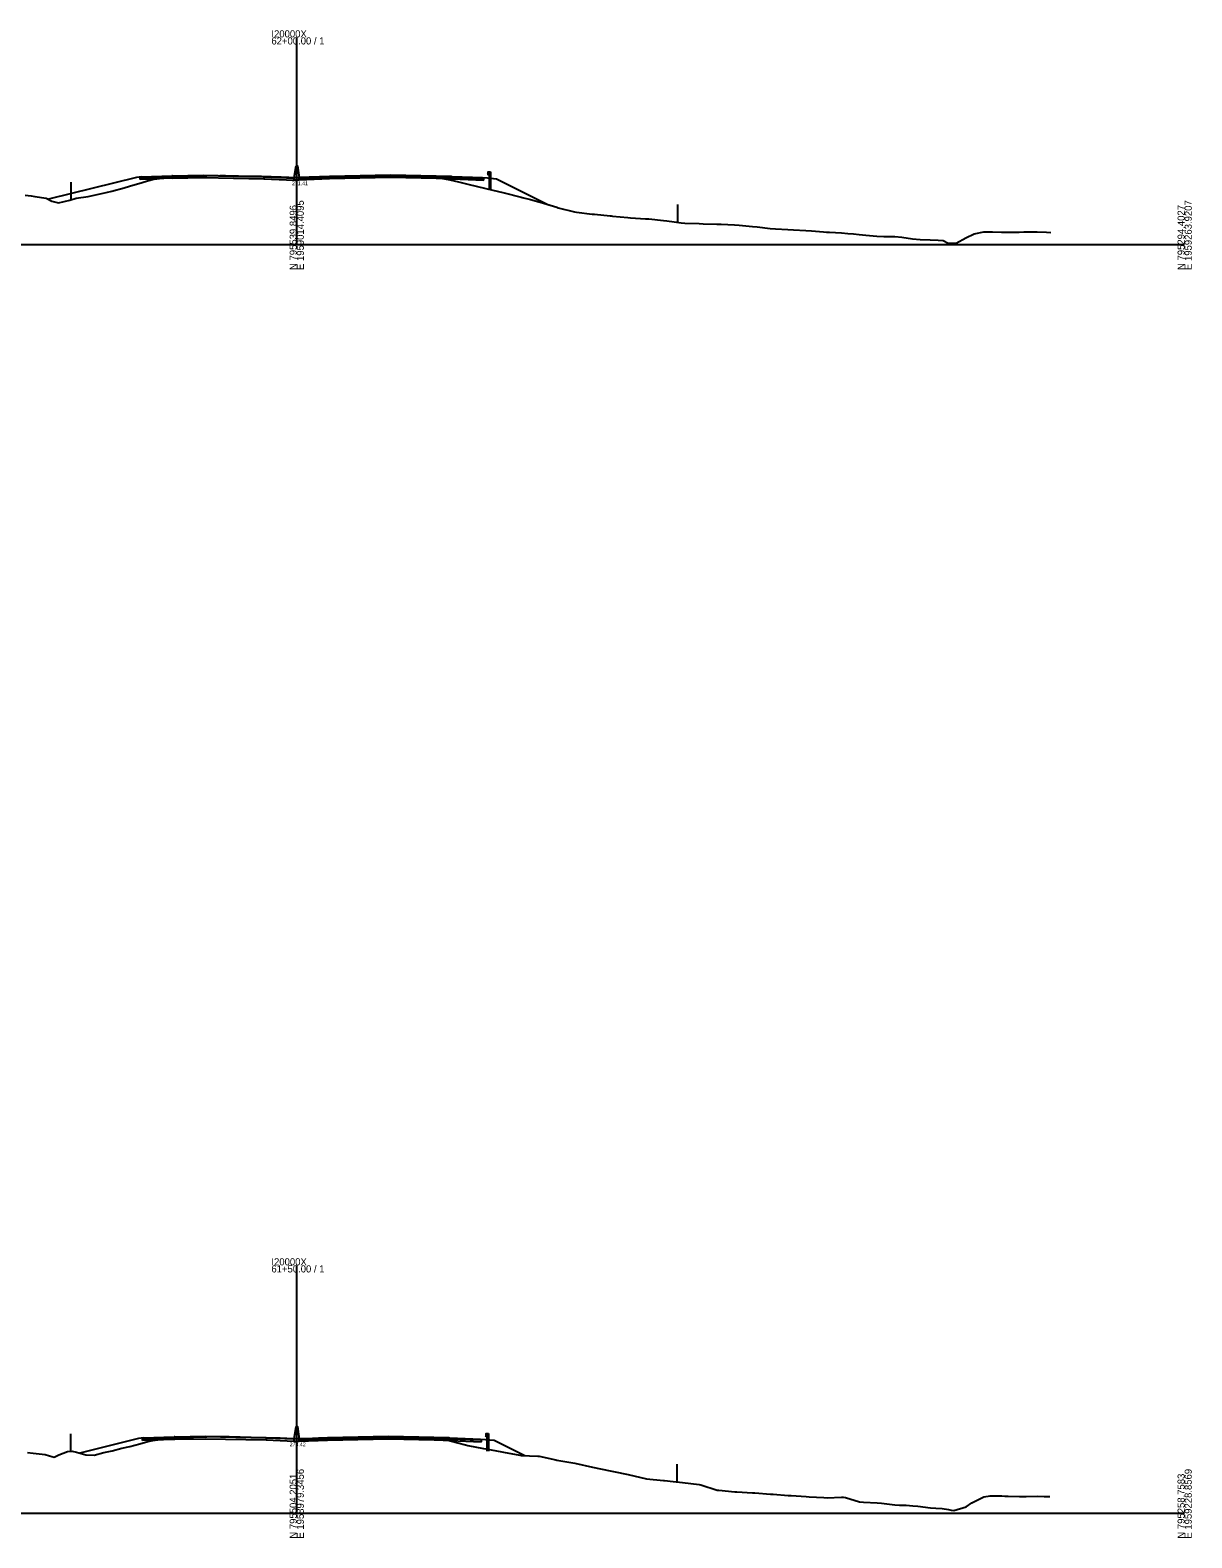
# Model space of a CAD drawing. Extents: x -4026 to 9638, y -10 to 19609.
# Drawn here: x -1755 to -1297, y 11490 to 12085 of the extents above; entities that cross this region are included whole.
import ezdxf

# ---------------------------------------------------------------- set-up
doc = ezdxf.new("R2010")
doc.units = 0
for name, color, linetype in [('RD_EX_Fence_Other', 7, 'Continuous'), ('RD_GPK_XS_Cell', 7, 'Continuous'), ('RD_XS_Base', 7, 'Continuous'), ('RD_XS_ExGround', 7, 'Continuous'), ('RD_XS_GR', 7, 'Continuous'), ('RD_XS_Greenside', 7, 'Continuous'), ('RD_XS_MedBWall', 7, 'Continuous'), ('RD_XS_Pave', 7, 'Continuous'), ('RD_XS_PaveOvlay', 7, 'Continuous'), ('RD_XS_TX_Elev_EX', 7, 'Continuous')]:
    doc.layers.add(name, color=color, linetype=linetype)

msp = doc.modelspace()

# ---------------------------------------------------------------- linework, layer by layer
at = {"layer": 'RD_EX_Fence_Other'}
for p, q in [((-1739.02, 12024.66), (-1739.02, 12017.66)), ((-1499.97, 12015.81), (-1499.97, 12008.81)), ((-1739.19, 11531.36), (-1739.19, 11524.36)), ((-1500.17, 11519.37), (-1500.17, 11512.37))]:
    msp.add_line(p, q, dxfattribs=at)
at = {"layer": 'RD_GPK_XS_Cell'}
for p, q in [((-1650, 12000), (-1650, 12081.68)), ((-2000, 12000), (-1650, 12000)), ((-1650, 12000), (-1300, 12000)), ((-1650, 11500), (-1650, 11597.7)), ((-2000, 11500), (-1650, 11500)), ((-1650, 11500), (-1300, 11500))]:
    msp.add_line(p, q, dxfattribs=at)
at = {"layer": 'RD_XS_Base'}
for points in [[(-1662.95, 12026.58), (-1686.95, 12027.06), (-1698.96, 12026.81)], [(-1637.05, 12026.58), (-1613, 12027.06), (-1589.04, 12026.58)], [(-1711.71, 12026.32), (-1711.21, 12026.33), (-1699.21, 12026.81)], [(-1711.71, 12025.65), (-1711.71, 12026.32)], [(-1699.21, 12026.14), (-1711.71, 12025.65)], [(-1699.21, 12026.81), (-1698.96, 12026.81)], [(-1699.21, 12026.14), (-1699.21, 12026.81)], [(-1698.96, 12026.14), (-1699.21, 12026.14)], [(-1698.96, 12026.81), (-1698.96, 12026.14)], [(-1698.96, 12026.14), (-1686.95, 12026.39), (-1662.95, 12025.91)], [(-1651, 12026.11), (-1662.95, 12026.58)], [(-1662.95, 12026.58), (-1662.95, 12025.91)], [(-1662.95, 12025.91), (-1651, 12025.44)], [(-1651, 12025.44), (-1651, 12026.11)], [(-1649, 12026.09), (-1637.05, 12026.58)], [(-1649, 12025.42), (-1649, 12026.09)], [(-1637.05, 12025.91), (-1649, 12025.42)], [(-1637.05, 12025.91), (-1637.05, 12026.58)], [(-1589.04, 12025.91), (-1613, 12026.39), (-1637.05, 12025.91)], [(-1589.04, 12026.58), (-1588.79, 12026.57)], [(-1589.04, 12025.91), (-1589.04, 12026.58)], [(-1588.79, 12025.9), (-1589.04, 12025.91)], [(-1588.79, 12026.57), (-1588.79, 12025.9)], [(-1576.29, 12026.08), (-1576.79, 12026.1), (-1588.79, 12026.57)], [(-1588.79, 12025.9), (-1576.29, 12025.41)], [(-1576.29, 12025.41), (-1576.29, 12026.08)], [(-1710.87, 11529.31), (-1710.37, 11529.33), (-1698.37, 11529.8)], [(-1710.87, 11528.64), (-1710.87, 11529.31)], [(-1698.37, 11529.13), (-1710.87, 11528.64)], [(-1698.37, 11529.8), (-1698.12, 11529.81)], [(-1698.37, 11529.13), (-1698.37, 11529.8)], [(-1698.12, 11529.14), (-1698.37, 11529.13)], [(-1662.12, 11529.57), (-1686.12, 11530.06), (-1698.12, 11529.81)], [(-1698.12, 11529.81), (-1698.12, 11529.14)], [(-1698.12, 11529.14), (-1686.12, 11529.39), (-1662.12, 11528.9)], [(-1651, 11529.14), (-1662.12, 11529.57)], [(-1662.12, 11529.57), (-1662.12, 11528.9)], [(-1662.12, 11528.9), (-1651, 11528.47)], [(-1651, 11528.47), (-1651, 11529.14)], [(-1649, 11528.92), (-1637.88, 11529.38)], [(-1649, 11528.25), (-1649, 11528.92)], [(-1637.88, 11528.71), (-1649, 11528.25)], [(-1637.88, 11529.38), (-1613.88, 11529.86), (-1589.88, 11529.38)], [(-1637.88, 11528.71), (-1637.88, 11529.38)], [(-1589.88, 11528.71), (-1613.88, 11529.19), (-1637.88, 11528.71)], [(-1589.88, 11529.38), (-1589.63, 11529.37)], [(-1589.88, 11528.71), (-1589.88, 11529.38)], [(-1589.63, 11528.7), (-1589.88, 11528.71)], [(-1589.63, 11529.37), (-1589.63, 11528.7)], [(-1577.13, 11528.87), (-1577.63, 11528.89), (-1589.63, 11529.37)], [(-1589.63, 11528.7), (-1577.13, 11528.2)], [(-1577.13, 11528.2), (-1577.13, 11528.87)]]:
    msp.add_lwpolyline(points, dxfattribs=at)
at = {"layer": 'RD_XS_ExGround'}
for points in [[(-1757.02, 12019.49), (-1754.68, 12019.17), (-1753.22, 12018.98), (-1748.76, 12018.36), (-1746.54, 12017.17), (-1743.93, 12016.42), (-1739.41, 12017.55), (-1736.91, 12018.29), (-1732.28, 12018.99), (-1731.08, 12019.24), (-1729.9, 12019.53), (-1725.15, 12020.56), (-1722.89, 12021.09), (-1718.02, 12022.4), (-1715.87, 12022.98), (-1710.89, 12024.51), (-1708.86, 12025.13), (-1706.33, 12025.8), (-1701.71, 12026.37), (-1700.18, 12026.56), (-1696.84, 12026.72), (-1690.58, 12027), (-1680.37, 12027.21), (-1679.28, 12027.23), (-1678.06, 12027.21), (-1667.9, 12027.01), (-1663.91, 12026.92), (-1656.21, 12026.76), (-1653.1, 12026.55), (-1651.07, 12026.41), (-1650, 12026.41), (-1647.09, 12026.42), (-1641.56, 12026.68), (-1633.56, 12026.86), (-1629.64, 12026.95), (-1624.55, 12027.03), (-1617.85, 12027.1), (-1612.48, 12027), (-1606.68, 12026.86), (-1600.12, 12026.53), (-1598.21, 12026.44), (-1593.19, 12026.13), (-1589.63, 12025.57), (-1586.2, 12024.7), (-1582.55, 12023.77), (-1575.42, 12022.18), (-1568.29, 12020.36), (-1561.57, 12018.74), (-1561.16, 12018.63), (-1557.83, 12017.72), (-1554.56, 12016.85), (-1554.03, 12016.7), (-1547.54, 12014.71), (-1546.9, 12014.52), (-1540.53, 12012.93), (-1539.77, 12012.77), (-1533.52, 12012.03), (-1532.64, 12011.97), (-1526.5, 12011.35), (-1526.01, 12011.32), (-1525.51, 12011.26), (-1519.49, 12010.69), (-1518.38, 12010.61), (-1512.47, 12010.2), (-1511.25, 12010.1), (-1505.46, 12009.48), (-1504.12, 12009.31), (-1501.26, 12008.99), (-1498.45, 12008.61), (-1496.99, 12008.5), (-1491.43, 12008.33), (-1489.86, 12008.24), (-1484.42, 12008.08), (-1482.73, 12008.05), (-1477.41, 12007.82), (-1475.6, 12007.67), (-1470.39, 12007.17), (-1468.47, 12006.99), (-1463.38, 12006.4), (-1461.34, 12006.21), (-1456.36, 12006), (-1454.21, 12005.86), (-1449.35, 12005.5), (-1447.08, 12005.37), (-1442.34, 12004.98), (-1441.16, 12004.91), (-1439.96, 12004.87), (-1435.32, 12004.59), (-1432.83, 12004.36), (-1430.55, 12004.2), (-1428.31, 12003.99), (-1427.01, 12003.84), (-1425.7, 12003.68), (-1421.3, 12003.28), (-1418.57, 12003.15), (-1414.28, 12003.15), (-1411.44, 12002.9), (-1407.27, 12002.31), (-1404.31, 12001.99), (-1400.25, 12001.88), (-1397.18, 12001.77), (-1395.19, 12001.64), (-1393.24, 12000.6), (-1390.05, 12000.62), (-1386.23, 12002.61), (-1382.92, 12004.25), (-1379.21, 12005.06), (-1375.79, 12005.1), (-1372.2, 12004.93), (-1368.66, 12004.88), (-1366.91, 12004.91), (-1365.19, 12004.95), (-1363.37, 12004.99), (-1361.53, 12005.01), (-1358.17, 12005.01), (-1354.4, 12004.9), (-1352.76, 12004.83)], [(-1756.16, 11523.89), (-1753.87, 11523.66), (-1752.71, 11523.54), (-1749.17, 11523.17), (-1747.46, 11522.68), (-1745.63, 11522.11), (-1743.84, 11523.07), (-1740.33, 11524.28), (-1738.56, 11524.41), (-1736.82, 11524.11), (-1733.2, 11522.96), (-1729.81, 11522.87), (-1726.07, 11523.93), (-1722.8, 11524.66), (-1718.94, 11525.61), (-1715.78, 11526.33), (-1711.81, 11527.35), (-1708.77, 11528.24), (-1706.74, 11528.73), (-1702.82, 11529.25), (-1701.24, 11529.48), (-1700.06, 11529.64), (-1695.5, 11529.81), (-1690.68, 11530.01), (-1680.23, 11530.22), (-1679.41, 11530.24), (-1676.69, 11530.19), (-1668.01, 11530.01), (-1656.57, 11529.78), (-1651.11, 11529.41), (-1650, 11529.42), (-1648.14, 11529.44), (-1647.12, 11529.46), (-1646.21, 11529.51), (-1641.4, 11529.76), (-1634.53, 11529.9), (-1629.74, 11530), (-1624.27, 11530.08), (-1617.92, 11530.17), (-1612.48, 11530.04), (-1606.55, 11529.91), (-1602.45, 11529.68), (-1598.31, 11529.47), (-1594.55, 11529.07), (-1592.28, 11528.86), (-1591.54, 11528.78), (-1591.17, 11528.74), (-1590.06, 11528.62), (-1589.54, 11528.48), (-1583.47, 11526.91), (-1582.52, 11526.71), (-1576.34, 11525.53), (-1575.51, 11525.37), (-1569.21, 11524.15), (-1568.49, 11524.06), (-1562.08, 11522.92), (-1561.48, 11522.82), (-1554.95, 11522.54), (-1554.47, 11522.48), (-1547.82, 11521.02), (-1547.45, 11520.96), (-1540.44, 11519.72), (-1533.43, 11518.18), (-1526.41, 11516.76), (-1525.2, 11516.51), (-1519.3, 11515.31), (-1512.17, 11513.63), (-1505.37, 11512.88), (-1505.04, 11512.85), (-1501.67, 11512.52), (-1497.91, 11512.16), (-1491.34, 11511.35), (-1490.78, 11511.19), (-1484.33, 11509.15), (-1483.65, 11509.05), (-1477.32, 11508.45), (-1476.52, 11508.41), (-1470.3, 11508.11), (-1469.39, 11508.05), (-1463.29, 11507.58), (-1462.26, 11507.48), (-1456.28, 11507.03), (-1455.13, 11506.97), (-1449.26, 11506.54), (-1448, 11506.44), (-1442.25, 11506.17), (-1440.87, 11506.07), (-1435.23, 11506.34), (-1434.5, 11506.39), (-1433.74, 11506.18), (-1428.22, 11504.55), (-1426.61, 11504.32), (-1421.21, 11504.05), (-1419.48, 11503.91), (-1414.19, 11503.31), (-1412.35, 11503.25), (-1409.75, 11503.15), (-1407.18, 11502.97), (-1405.22, 11502.73), (-1400.17, 11502.13), (-1398.09, 11502.02), (-1395.6, 11501.85), (-1393.15, 11501.43), (-1392.07, 11501.24), (-1390.97, 11501.15), (-1386.14, 11502.58), (-1383.84, 11504.05), (-1379.12, 11506.43), (-1376.71, 11506.86), (-1372.11, 11506.83), (-1370.85, 11506.77), (-1369.58, 11506.7), (-1365.1, 11506.63), (-1362.45, 11506.65), (-1358.08, 11506.67), (-1355.32, 11506.65), (-1353.18, 11506.63)]]:
    msp.add_lwpolyline(points, dxfattribs=at)
at = {"layer": 'RD_XS_GR'}
for points in [[(-1574.55, 12028.66), (-1574.79, 12028.36)], [(-1574.79, 12028.36), (-1574.56, 12028.06)], [(-1574.56, 12028.06), (-1574.79, 12027.78)], [(-1574.79, 12027.78), (-1574.55, 12027.48)], [(-1574.55, 12027.48), (-1574.55, 12028.66)], [(-1574.55, 12028.66), (-1574.06, 12028.66)], [(-1574.06, 12027.48), (-1574.55, 12027.48)], [(-1574.06, 12028.66), (-1573.57, 12028.66)], [(-1574.06, 12026.2), (-1574.06, 12028.66)], [(-1574.06, 12028.66), (-1574.06, 12027.48)], [(-1573.57, 12028.66), (-1573.57, 12026.16)], [(-1574.06, 12021.7), (-1574.06, 12026.2)], [(-1574.06, 12026.2), (-1573.57, 12026.16)], [(-1573.57, 12026.16), (-1574.06, 12026.2)], [(-1573.57, 12026.16), (-1573.57, 12021.7)], [(-1575.38, 11531.46), (-1575.62, 11531.16)], [(-1575.62, 11531.16), (-1575.39, 11530.86)], [(-1575.39, 11530.86), (-1575.62, 11530.58)], [(-1575.62, 11530.58), (-1575.38, 11530.28)], [(-1575.38, 11530.28), (-1575.38, 11531.46)], [(-1575.38, 11531.46), (-1574.89, 11531.46)], [(-1574.89, 11530.28), (-1575.38, 11530.28)], [(-1574.89, 11531.46), (-1574.4, 11531.46)], [(-1574.89, 11529), (-1574.89, 11531.46)], [(-1574.89, 11531.46), (-1574.89, 11530.28)], [(-1574.89, 11524.5), (-1574.89, 11529)], [(-1574.89, 11529), (-1574.4, 11528.96)], [(-1574.4, 11528.96), (-1574.89, 11529)], [(-1574.4, 11531.46), (-1574.4, 11528.96)], [(-1574.4, 11528.96), (-1574.4, 11524.5)]]:
    msp.add_lwpolyline(points, dxfattribs=at)
at = {"layer": 'RD_XS_Greenside'}
for points in [[(-1713.21, 12026.51), (-1747.81, 12017.86)], [(-1711.21, 12026.67), (-1713.21, 12026.51)], [(-1576.79, 12026.43), (-1574.79, 12026.26)], [(-1574.79, 12026.26), (-1571.29, 12025.97), (-1550.71, 12015.68)], [(-1712.37, 11529.5), (-1735.56, 11523.71)], [(-1710.37, 11529.66), (-1712.37, 11529.5)], [(-1577.63, 11529.23), (-1575.63, 11529.06)], [(-1575.63, 11529.06), (-1572.13, 11528.77), (-1560.11, 11522.76)]]:
    msp.add_lwpolyline(points, dxfattribs=at)
at = {"layer": 'RD_XS_MedBWall'}
for points in [[(-1651, 12026.44), (-1650.25, 12031.11)], [(-1650.25, 12031.11), (-1649.75, 12031.11), (-1649, 12026.41)], [(-1651, 12025.41), (-1651, 12026.11), (-1651, 12026.44)], [(-1649, 12025.41), (-1651, 12025.41)], [(-1649, 12026.41), (-1649, 12026.09), (-1649, 12025.41)], [(-1651, 11529.46), (-1650.25, 11534.13)], [(-1650.25, 11534.13), (-1649.75, 11534.13), (-1649, 11529.25)], [(-1651, 11528.25), (-1651, 11529.14), (-1651, 11529.46)], [(-1649, 11528.25), (-1651, 11528.25)], [(-1649, 11529.25), (-1649, 11528.92), (-1649, 11528.25)]]:
    msp.add_lwpolyline(points, dxfattribs=at)
at = {"layer": 'RD_XS_Pave'}
for points in [[(-1698.96, 12026.98), (-1686.95, 12027.23), (-1662.95, 12026.75)], [(-1662.95, 12026.58), (-1686.95, 12027.06), (-1698.96, 12026.81)], [(-1589.04, 12026.75), (-1613, 12027.23), (-1637.05, 12026.75)], [(-1637.05, 12026.58), (-1613, 12027.06), (-1589.04, 12026.58)], [(-1711.21, 12026.5), (-1699.21, 12026.98)], [(-1699.21, 12026.81), (-1711.21, 12026.33)], [(-1711.21, 12026.33), (-1711.21, 12026.5)], [(-1699.21, 12026.98), (-1698.96, 12026.98)], [(-1699.21, 12026.81), (-1699.21, 12026.98)], [(-1698.96, 12026.81), (-1699.21, 12026.81)], [(-1698.96, 12026.98), (-1698.96, 12026.81)], [(-1662.95, 12026.75), (-1662.95, 12026.58)], [(-1662.95, 12026.75), (-1651, 12026.28)], [(-1651, 12026.11), (-1662.95, 12026.58)], [(-1651, 12026.28), (-1651, 12026.11)], [(-1637.05, 12026.75), (-1649, 12026.26)], [(-1649, 12026.09), (-1637.05, 12026.58)], [(-1649, 12026.26), (-1649, 12026.09)], [(-1637.05, 12026.75), (-1637.05, 12026.58)], [(-1589.04, 12026.75), (-1588.79, 12026.74)], [(-1589.04, 12026.58), (-1589.04, 12026.75)], [(-1588.79, 12026.57), (-1589.04, 12026.58)], [(-1588.79, 12026.74), (-1588.79, 12026.57)], [(-1576.79, 12026.26), (-1588.79, 12026.74)], [(-1588.79, 12026.57), (-1576.79, 12026.1)], [(-1576.79, 12026.1), (-1576.79, 12026.26)], [(-1710.37, 11529.5), (-1698.37, 11529.97)], [(-1698.37, 11529.8), (-1710.37, 11529.33)], [(-1710.37, 11529.33), (-1710.37, 11529.5)], [(-1698.37, 11529.97), (-1698.12, 11529.98)], [(-1698.37, 11529.8), (-1698.37, 11529.97)], [(-1698.12, 11529.81), (-1698.37, 11529.8)], [(-1698.12, 11529.98), (-1686.12, 11530.22), (-1662.12, 11529.74)], [(-1662.12, 11529.57), (-1686.12, 11530.06), (-1698.12, 11529.81)], [(-1698.12, 11529.98), (-1698.12, 11529.81)], [(-1662.12, 11529.74), (-1662.12, 11529.57)], [(-1662.12, 11529.74), (-1651, 11529.31)], [(-1651, 11529.14), (-1662.12, 11529.57)], [(-1651, 11529.31), (-1651, 11529.14)], [(-1637.88, 11529.55), (-1649, 11529.09)], [(-1649, 11528.92), (-1637.88, 11529.38)], [(-1649, 11529.09), (-1649, 11528.92)], [(-1589.88, 11529.55), (-1613.88, 11530.03), (-1637.88, 11529.55)], [(-1637.88, 11529.38), (-1613.88, 11529.86), (-1589.88, 11529.38)], [(-1637.88, 11529.55), (-1637.88, 11529.38)], [(-1589.88, 11529.55), (-1589.63, 11529.54)], [(-1589.88, 11529.38), (-1589.88, 11529.55)], [(-1589.63, 11529.37), (-1589.88, 11529.38)], [(-1589.63, 11529.54), (-1589.63, 11529.37)], [(-1577.63, 11529.06), (-1589.63, 11529.54)], [(-1589.63, 11529.37), (-1577.63, 11528.89)], [(-1577.63, 11528.89), (-1577.63, 11529.06)]]:
    msp.add_lwpolyline(points, dxfattribs=at)
at = {"layer": 'RD_XS_PaveOvlay'}
for points in [[(-1711.21, 12026.67), (-1699.21, 12027.15)], [(-1699.21, 12027.15), (-1699.21, 12026.98)], [(-1698.96, 12027.15), (-1699.21, 12027.15)], [(-1698.96, 12027.15), (-1686.95, 12027.39), (-1662.95, 12026.91)], [(-1662.95, 12026.75), (-1686.95, 12027.23), (-1698.96, 12026.98)], [(-1698.96, 12026.98), (-1698.96, 12027.15)], [(-1589.04, 12026.91), (-1613, 12027.39), (-1637.05, 12026.91)], [(-1637.05, 12026.75), (-1613, 12027.23), (-1589.04, 12026.75)], [(-1699.21, 12026.98), (-1711.21, 12026.5)], [(-1711.21, 12026.5), (-1711.21, 12026.67)], [(-1699.21, 12026.98), (-1698.96, 12026.98)], [(-1662.95, 12026.91), (-1662.95, 12026.75)], [(-1662.95, 12026.91), (-1651, 12026.44)], [(-1651, 12026.28), (-1662.95, 12026.75)], [(-1651, 12026.44), (-1651, 12026.28)], [(-1637.05, 12026.91), (-1649, 12026.41)], [(-1649, 12026.26), (-1637.05, 12026.75)], [(-1649, 12026.41), (-1649, 12026.26)], [(-1637.05, 12026.91), (-1637.05, 12026.75)], [(-1589.04, 12026.75), (-1589.04, 12026.91)], [(-1589.04, 12026.91), (-1588.79, 12026.91)], [(-1588.79, 12026.74), (-1589.04, 12026.75)], [(-1588.79, 12026.91), (-1588.79, 12026.74)], [(-1588.79, 12026.91), (-1576.79, 12026.43)], [(-1576.79, 12026.26), (-1588.79, 12026.74)], [(-1576.79, 12026.43), (-1576.79, 12026.26)], [(-1710.37, 11529.66), (-1698.37, 11530.14)], [(-1698.37, 11529.97), (-1710.37, 11529.5)], [(-1710.37, 11529.5), (-1710.37, 11529.66)], [(-1698.12, 11530.15), (-1698.37, 11530.14)], [(-1698.37, 11530.14), (-1698.37, 11529.97)], [(-1698.37, 11529.97), (-1698.12, 11529.98)], [(-1698.12, 11530.15), (-1686.12, 11530.39), (-1662.12, 11529.91)], [(-1662.12, 11529.74), (-1686.12, 11530.22), (-1698.12, 11529.98)], [(-1698.12, 11529.98), (-1698.12, 11530.15)], [(-1662.12, 11529.91), (-1662.12, 11529.74)], [(-1662.12, 11529.91), (-1651, 11529.46)], [(-1651, 11529.31), (-1662.12, 11529.74)], [(-1651, 11529.46), (-1651, 11529.31)], [(-1637.88, 11529.71), (-1649, 11529.25)], [(-1649, 11529.09), (-1637.88, 11529.55)], [(-1649, 11529.25), (-1649, 11529.09)], [(-1589.88, 11529.71), (-1613.88, 11530.19), (-1637.88, 11529.71)], [(-1637.88, 11529.55), (-1613.88, 11530.03), (-1589.88, 11529.55)], [(-1637.88, 11529.71), (-1637.88, 11529.55)], [(-1589.88, 11529.55), (-1589.88, 11529.71)], [(-1589.88, 11529.71), (-1589.63, 11529.71)], [(-1589.63, 11529.54), (-1589.88, 11529.55)], [(-1589.63, 11529.71), (-1589.63, 11529.54)], [(-1589.63, 11529.71), (-1577.63, 11529.23)], [(-1577.63, 11529.06), (-1589.63, 11529.54)], [(-1577.63, 11529.23), (-1577.63, 11529.06)]]:
    msp.add_lwpolyline(points, dxfattribs=at)

# ---------------------------------------------------------------- texts
at = {"layer": 'RD_GPK_XS_Cell'}
for s, p in [('62+00.00 / 1', (-1660, 12078.88)), ('I20000X', (-1660, 12081.68)), ('I20000X', (-1660, 11597.7)), ('61+50.00 / 1', (-1660, 11594.9))]:
    msp.add_text(s, height=2.8, dxfattribs=at).set_placement(p)
for s, p in [('N 795539.8496', (-1650, 11990)), ('E 1959014.4095', (-1647.2, 11990)), ('N 795294.4027', (-1300, 11990)), ('E 1959263.9207', (-1297.2, 11990)), ('E 1958979.3456', (-1647.2, 11490)), ('E 1959228.8569', (-1297.2, 11490)), ('N 795504.2051', (-1650, 11490)), ('N 795258.7583', (-1300, 11490))]:
    msp.add_text(s, height=2.8, rotation=90, dxfattribs=at).set_placement(p)
at = {"layer": 'RD_XS_TX_Elev_EX'}
for s, p in [('271.41', (-1651.91, 12023.41)), ('273.42', (-1652.8, 11526.42))]:
    msp.add_text(s, height=1.5, dxfattribs=at).set_placement(p)

doc.saveas('drawing.dxf')
